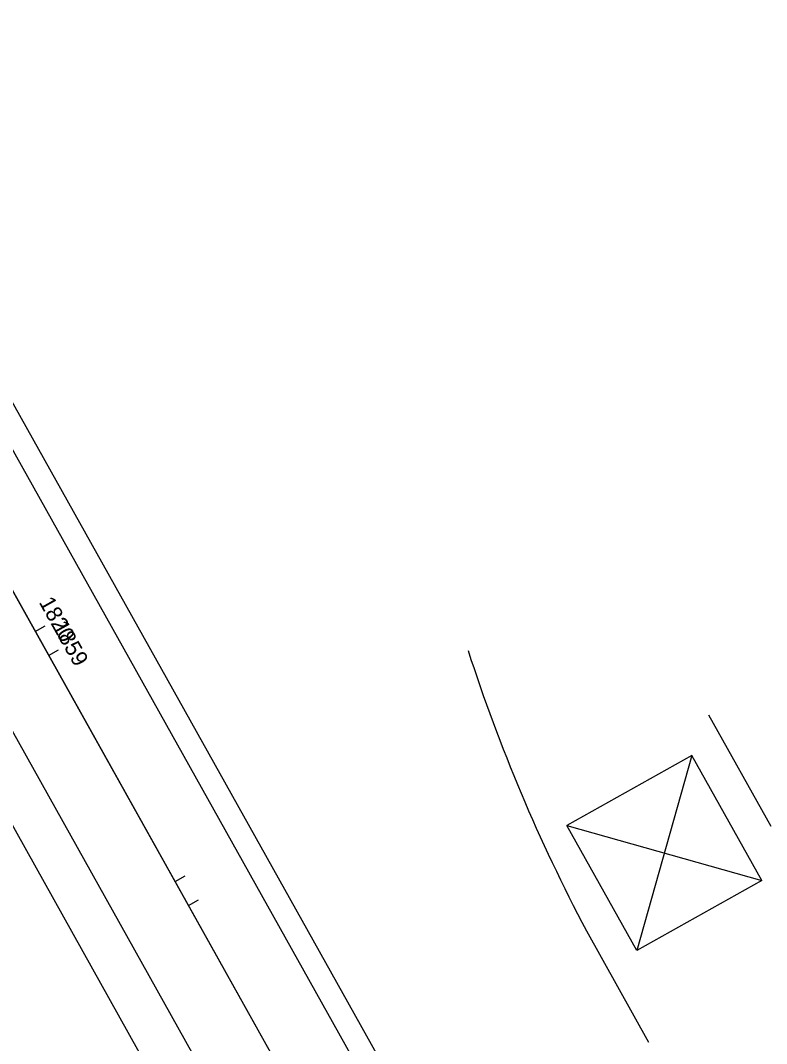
# Model space of a CAD drawing. Extents: x 6334 to 41599, y 9030 to 59113.
# Drawn here: x 21179.4 to 21309.6, y 34183.1 to 34361.6 of the extents above; entities that cross this region are included whole.
import ezdxf

# ---------------------------------------------------------------- set-up
doc = ezdxf.new("R2010")
doc.units = 0
for name, color, linetype in [('GE_X_CL_20', 7, 'Continuous'), ('GK_Visualization', 7, 'Continuous'), ('PM_X_Lane_Line', 7, 'Continuous'), ('PV_X_EOP', 7, 'Continuous'), ('PV_X_Shoulder', 7, 'Continuous'), ('RD_X_GR_Lt', 7, 'Continuous'), ('UT_X_Electric_Cells', 7, 'Continuous')]:
    doc.layers.add(name, color=color, linetype=linetype)

msp = doc.modelspace()

# ---------------------------------------------------------------- linework, layer by layer
at = {"layer": 'GE_X_CL_20'}
for p, q in [((21120.4, 34365.07), (21585.88, 33532.76)), ((21181.95, 34255), (21183.7, 34255.98)), ((21184.28, 34250.84), (21186.02, 34251.82)), ((21206.36, 34211.36), (21208.1, 34212.34)), ((21208.68, 34207.21), (21210.43, 34208.18))]:
    msp.add_line(p, q, dxfattribs=at)
at = {"layer": 'GK_Visualization'}
for p in [(21120.28, 34365.28), (21120.4, 34365.07)]:
    msp.add_line(p, (21585.88, 33532.76), dxfattribs=at)
at = {"layer": 'PM_X_Lane_Line'}
msp.add_line((21120.4, 34365.07), (21585.88, 33532.76), dxfattribs=at)
msp.add_line((21120.4, 34365.07), (21585.88, 33532.76), dxfattribs=at)
at = {"layer": 'PV_X_EOP'}
for p, q in [((21130.87, 34370.92), (21596.35, 33538.62)), ((21109.92, 34359.21), (21575.4, 33526.9))]:
    msp.add_line(p, q, dxfattribs=at)
at = {"layer": 'PV_X_Shoulder'}
for p, q in [((21134.36, 34372.88), (21599.84, 33540.57)), ((21102.94, 34355.3), (21568.42, 33523))]:
    msp.add_line(p, q, dxfattribs=at)
at = {"layer": 'RD_X_GR_Lt'}
for p, q in [((21310.37, 34220.97), (21299.51, 34240.38)), ((21278.12, 34202.78), (21288.98, 34183.37))]:
    msp.add_line(p, q, dxfattribs=at)
msp.add_arc((21550.44, 34346.56), 307.95, 197.9442, 207.8322, dxfattribs=at)
at = {"layer": 'UT_X_Electric_Cells'}
for p, q in [((21296.54, 34233.36), (21274.72, 34221.16)), ((21296.54, 34233.36), (21286.92, 34199.34)), ((21308.74, 34211.54), (21296.54, 34233.36)), ((21274.72, 34221.16), (21308.74, 34211.54)), ((21286.92, 34199.34), (21274.72, 34221.16)), ((21308.74, 34211.54), (21286.92, 34199.34))]:
    msp.add_line(p, q, dxfattribs=at)

# ---------------------------------------------------------------- texts
at = {"layer": 'GE_X_CL_20'}
for s, p in [('1820', (21182.53, 34260.11)), ('1859', (21184.87, 34255.93))]:
    msp.add_text(s, height=2.8, rotation=299.2167, dxfattribs=at).set_placement(p)

doc.saveas('drawing.dxf')
